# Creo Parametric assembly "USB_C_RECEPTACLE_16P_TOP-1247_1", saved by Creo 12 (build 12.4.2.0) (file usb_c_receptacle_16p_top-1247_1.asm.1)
Units: Custom; MM, KILOGRAM, SECS

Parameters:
  PTC_WM_ITERATION = "0"
  PTC_WM_VERSION = "-.0"
  PTC_WM_LIFECYCLE_STATE = "In Work"
  PTC_WM_LIFECYCLE = "MO_CADDocument"
  PTC_WM_CREATED_BY = "Maximilian Roepper (Z0017RMS: MO)"
  PTC_WM_CREATED_ON = "18-Sep-26 11:36:42 AM"
  PTC_WM_MODIFIED_BY = "Maximilian Roepper (Z0017RMS: MO)"
  PTC_WM_MODIFIED_ON = "18-Sep-26 11:36:46 AM"
  PDMLINKNUMBER = "PDM000071454904"
  PTC_WM_NUMBER = "PDM000071454904"

Other parameters: WEIGHT, WEIGHT_FACTOR, WEIGHT_ADD, MC_ERRORS, SUPPLIER

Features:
  1. coordinate system
  2. imported feature
  3. component "USB_C_RECEPTACLE_16P_TOP-1247_2"
  4. component "USB_C_RECEPTACLE_16P_TOP-1247_3"
  5. component "ESP32_WROOM_32D_KITV1_CASING__2"
  6. component "ESP32_WROOM_32D_KITV1_CASING__3"
  7. component "ESP32_WROOM_32D_KITV1_CASING__4"
  8. component "ESP32_WROOM_32D_KITV1_CASING__5"
  9. component "ESP32_WROOM_32D_KITV1_CASING__6"
  10. component "ESP32_WROOM_32D_KITV1_CASING__7"
  11. component "ESP32_WROOM_32D_KITV1_CASING__8"
  12. component "ESP32_WROOM_32D_KITV1_CASING__9"
  13. component "ESP32_WROOM_32D_KITV1_CASING_15"
  14. component "USB_C_RECEPTACLE_16P_TOP-1247_4"
  15. component "ESP32_WROOM_32D_KITV1_CASING_25"
  16. component "ESP32_WROOM_32D_KITV1_CASING_35"
  17. component "ESP32_WROOM_32D_KITV1_CASING_40"
  18. component "ESP32_WROOM_32D_KITV1_CASING_41"
  19. component "ESP32_WROOM_32D_KITV1_CASING_42"
  20. component "ESP32_WROOM_32D_KITV1_CASING_43"
  21. component "ESP32_WROOM_32D_KITV1_CASING_44"
  22. component "ESP32_WROOM_32D_KITV1_CASING_45"
  23. component "ESP32_WROOM_32D_KITV1_CASING_46"
  24. component "USB_C_RECEPTACLE_16P_TOP-1247_5"
  25. component "ESP32_WROOM_32D_KITV1_CASING_47"
  26. component "ESP32_WROOM_32D_KITV1_CASING_48"
  27. component "ESP32_WROOM_32D_KITV1_CASING_49"
  28. component "ESP32_WROOM_32D_KITV1_CASING_50"
  29. component "ESP32_WROOM_32D_KITV1_CASING_51"
  30. component "ESP32_WROOM_32D_KITV1_CASING_52"
  31. component "ESP32_WROOM_32D_KITV1_CASING_53"
  32. component "ESP32_WROOM_32D_KITV1_CASING_54"
  33. component "ESP32_WROOM_32D_KITV1_CASING_55"
  34. component "USB_C_RECEPTACLE_16P_TOP-1247_6"
  35. component "ESP32_WROOM_32D_KITV1_CASING_56"
  36. component "ESP32_WROOM_32D_KITV1_CASING_57"
  37. component "ESP32_WROOM_32D_KITV1_CASING_58"
  38. component "ESP32_WROOM_32D_KITV1_CASING_59"

Other named items: DRW_VIEW_ORG, ROUGH-GROB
